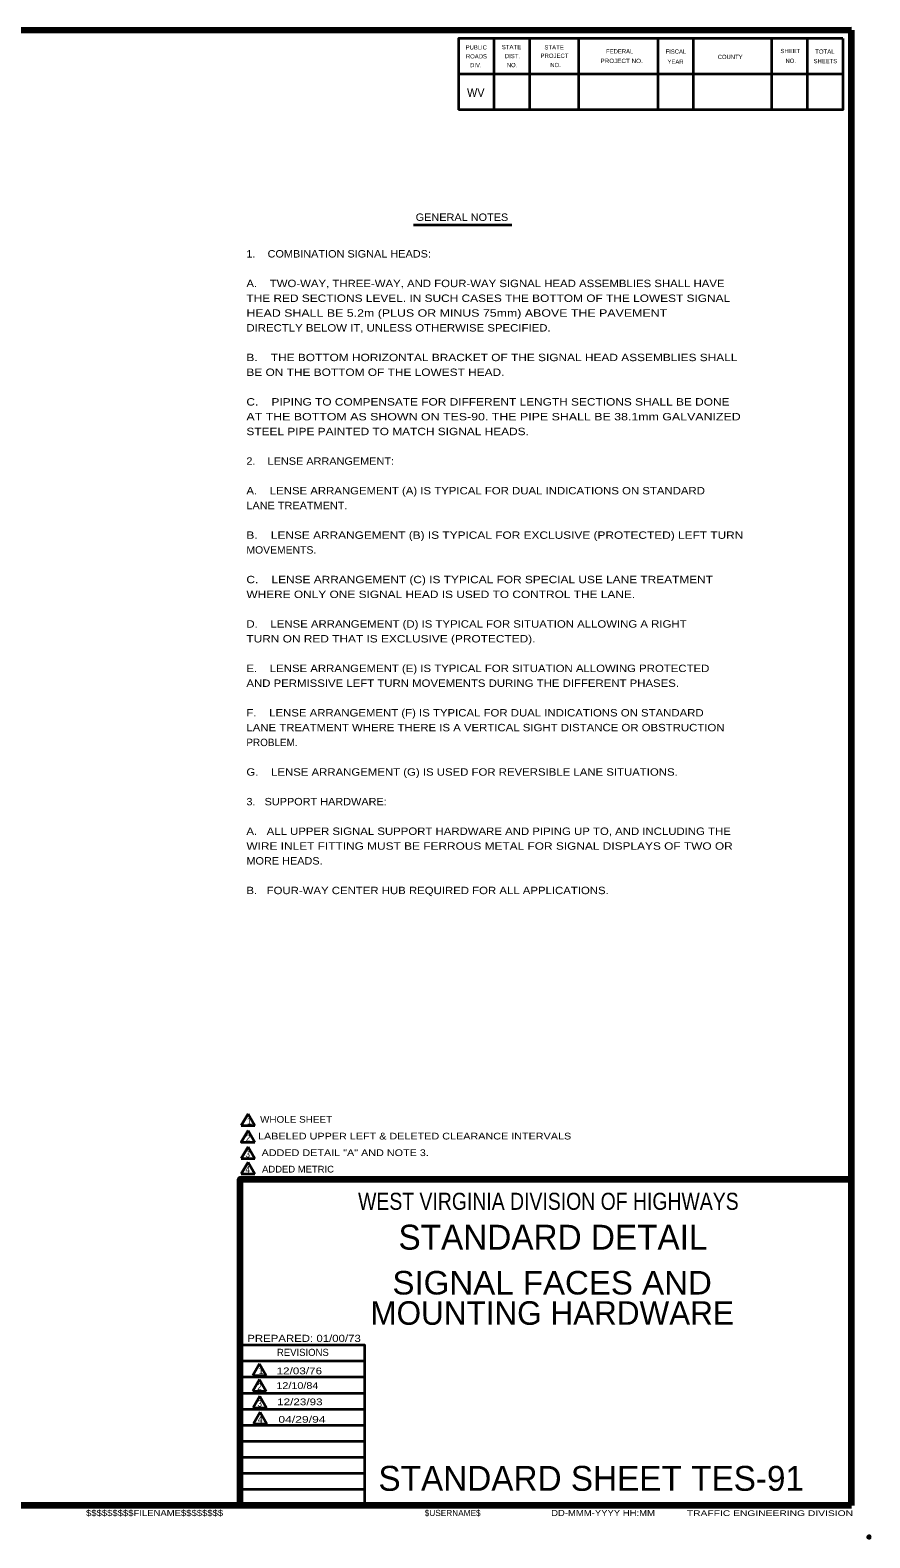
# Model space of a CAD drawing. Extents: x -382 to 473, y -132 to 412.
# Drawn here: x 174 to 473, y -132 to 406 of the extents above; entities that cross this region are included whole.
import ezdxf
from ezdxf.enums import TextEntityAlignment as Align

# ---------------------------------------------------------------- set-up
doc = ezdxf.new("R2010")
doc.units = 0
doc.header["$LTSCALE"] = 1.1
doc.header["$PDMODE"] = 32
doc.header["$PDSIZE"] = 0.55
doc.layers.add('1', color=7, linetype='Continuous', lineweight=53)
doc.layers.add('61', color=7, linetype='Continuous', lineweight=35)

msp = doc.modelspace()

# ---------------------------------------------------------------- linework, layer by layer
at = {"layer": '1', "lineweight": 158}
for q in [(466.693, 405.773), (466.693, -4.027), (-324.907, -120.327)]:
    msp.add_line((466.693, -120.327), q, dxfattribs=at)
at = {"layer": '1', "lineweight": 13}
msp.add_line((466.693, -120.327), (466.693, 405.773), dxfattribs=at)
at = {"layer": '1', "lineweight": 35}
for p, q in [((310.49, 336.296), (345.56, 336.296)), ((251.466, 19.314), (249.066, 15.157)), ((251.466, 19.314), (253.866, 15.157)), ((249.066, 15.157), (253.866, 15.157)), ((251.466, 13.329), (253.866, 9.172)), ((251.466, 7.523), (249.066, 3.367)), ((251.466, 7.523), (253.866, 3.367)), ((249.066, 3.367), (253.866, 3.367)), ((251.466, 2.033), (249.066, -2.123)), ((251.466, 2.033), (253.866, -2.123)), ((249.066, -2.123), (253.866, -2.123)), ((293.193, -68.927), (248.693, -68.927)), ((255.587, -69.839), (253.187, -73.996)), ((255.587, -69.839), (257.987, -73.996)), ((293.193, -74.627), (248.693, -74.627)), ((253.187, -73.996), (257.987, -73.996)), ((293.193, -80.427), (248.693, -80.427)), ((255.585, -75.449), (253.185, -79.606)), ((253.185, -79.606), (257.985, -79.606)), ((255.585, -75.449), (257.985, -79.606)), ((255.659, -81.36), (253.259, -85.517)), ((253.259, -85.517), (258.059, -85.517)), ((255.659, -81.36), (258.059, -85.517)), ((293.193, -86.127), (248.693, -86.127)), ((255.824, -87.07), (253.424, -91.227)), ((253.424, -91.227), (258.224, -91.227)), ((255.824, -87.07), (258.224, -91.227)), ((293.193, -91.827), (248.693, -91.827)), ((293.193, -97.527), (248.693, -97.527)), ((293.193, -103.227), (248.693, -103.227)), ((293.193, -108.927), (248.693, -108.927)), ((293.193, -114.627), (248.693, -114.627))]:
    msp.add_line(p, q, dxfattribs=at)
at = {"layer": '1', "lineweight": 158}
for points in [[(466.693, 405.773), (-325.007, 405.673), (-324.907, -120.327)], [(248.693, -120.327), (248.693, -4.027), (466.693, -4.027)]]:
    msp.add_lwpolyline(points, dxfattribs=at)
at = {"layer": '1', "lineweight": 35}
for points in [[(251.466, 13.329), (249.066, 9.172), (253.866, 9.172)], [(293.193, -120.327), (293.193, -63.227), (248.693, -63.227)]]:
    msp.add_lwpolyline(points, dxfattribs=at)
at = {"layer": '1'}
msp.add_point((472.993, -131.627), dxfattribs=at)
at = {"layer": '61'}
for p, q in [((339.193, 402.773), (339.193, 377.373)), ((351.893, 402.773), (351.893, 377.373)), ((369.293, 402.773), (369.293, 377.373)), ((397.593, 402.773), (397.593, 377.373)), ((410.293, 402.773), (410.293, 377.373)), ((438.193, 402.773), (438.193, 377.373)), ((450.893, 402.773), (450.893, 377.373)), ((463.593, 390.073), (326.493, 390.073))]:
    msp.add_line(p, q, dxfattribs=at)
at = {"layer": '61', "lineweight": 53}
for q in [(313.993, -120.327), (313.993, -120.327), (313.993, -120.327), (314.293, -120.327), (314.293, -120.327)]:
    msp.add_line((466.693, -120.327), q, dxfattribs=at)
at = {"layer": '61'}
for points in [[(463.593, 402.773), (326.493, 402.773), (326.493, 377.373)], [(463.593, 402.773), (463.593, 377.373), (326.493, 377.373)]]:
    msp.add_lwpolyline(points, dxfattribs=at)

# ---------------------------------------------------------------- texts
at = {"layer": '1'}
for s, height, width, p in [('WV', 3.048, 0.95, (329.593, 381.973)), ('1.    COMBINATION SIGNAL HEADS:', 2.64, 1.1, (250.896, 324.693)), ('A.    TWO-WAY, THREE-WAY, AND FOUR-WAY SIGNAL HEAD ASSEMBLIES SHALL HAVE', 2.64, 1.15, (250.896, 314.133)), ('THE RED SECTIONS LEVEL. IN SUCH CASES THE BOTTOM OF THE LOWEST SIGNAL', 2.64, 1.2, (250.896, 308.853)), ('HEAD SHALL BE 5.2m (PLUS OR MINUS 75mm) ABOVE THE PAVEMENT', 2.64, 1.25, (250.896, 303.573)), ('DIRECTLY BELOW IT, UNLESS OTHERWISE SPECIFIED.', 2.64, 1.15, (250.896, 298.293)), ('B.    THE BOTTOM HORIZONTAL BRACKET OF THE SIGNAL HEAD ASSEMBLIES SHALL', 2.64, 1.2, (250.896, 287.733)), ('BE ON THE BOTTOM OF THE LOWEST HEAD.', 2.64, 1.2, (250.896, 282.453)), ('C.    PIPING TO COMPENSATE FOR DIFFERENT LENGTH SECTIONS SHALL BE DONE', 2.64, 1.2, (250.896, 271.893)), ('AT THE BOTTOM AS SHOWN ON TES-90. THE PIPE SHALL BE 38.1mm GALVANIZED', 2.64, 1.25, (250.896, 266.613)), ('STEEL PIPE PAINTED TO MATCH SIGNAL HEADS.', 2.64, 1.2, (250.896, 261.333)), ('2.    LENSE ARRANGEMENT:', 2.64, 1.1, (250.896, 250.773)), ('A.    LENSE ARRANGEMENT (A) IS TYPICAL FOR DUAL INDICATIONS ON STANDARD', 2.64, 1.15, (250.896, 240.213)), ('LANE TREATMENT.', 2.64, 1.1, (250.896, 234.933)), ('B.    LENSE ARRANGEMENT (B) IS TYPICAL FOR EXCLUSIVE (PROTECTED) LEFT TURN', 2.64, 1.2, (250.896, 224.373)), ('MOVEMENTS.', 2.64, 1.05, (250.896, 219.093)), ('C.    LENSE ARRANGEMENT (C) IS TYPICAL FOR SPECIAL USE LANE TREATMENT', 2.64, 1.2, (250.896, 208.533)), ('WHERE ONLY ONE SIGNAL HEAD IS USED TO CONTROL THE LANE.', 2.64, 1.2, (250.896, 203.253)), ('D.    LENSE ARRANGEMENT (D) IS TYPICAL FOR SITUATION ALLOWING A RIGHT', 2.64, 1.15, (250.896, 192.693)), ('TURN ON RED THAT IS EXCLUSIVE (PROTECTED).', 2.64, 1.2, (250.896, 187.413)), ('E.    LENSE ARRANGEMENT (E) IS TYPICAL FOR SITUATION ALLOWING PROTECTED', 2.64, 1.15, (250.896, 176.853)), ('AND PERMISSIVE LEFT TURN MOVEMENTS DURING THE DIFFERENT PHASES.', 2.64, 1.15, (250.896, 171.573)), ('F.    LENSE ARRANGEMENT (F) IS TYPICAL FOR DUAL INDICATIONS ON STANDARD', 2.64, 1.15, (250.896, 161.013)), ('LANE TREATMENT WHERE THERE IS A VERTICAL SIGHT DISTANCE OR OBSTRUCTION', 2.64, 1.15, (250.896, 155.733)), ('G.    LENSE ARRANGEMENT (G) IS USED FOR REVERSIBLE LANE SITUATIONS.', 2.64, 1.15, (250.896, 139.893)), ('3.   SUPPORT HARDWARE:', 2.64, 1.1, (250.896, 129.333)), ('A.   ALL UPPER SIGNAL SUPPORT HARDWARE AND PIPING UP TO, AND INCLUDING THE', 2.64, 1.15, (250.896, 118.773)), ('WIRE INLET FITTING MUST BE FERROUS METAL FOR SIGNAL DISPLAYS OF TWO OR', 2.64, 1.2, (250.896, 113.493)), ('MORE HEADS.', 2.64, 1.1, (250.896, 108.213)), ('B.   FOUR-WAY CENTER HUB REQUIRED FOR ALL APPLICATIONS.', 2.64, 1.15, (250.896, 97.653)), ('PREPARED: 01/00/73', 2.537, 1.2, (251.193, -62.027)), ('12/03/76', 2.397, 1.3, (261.661, -73.553)), ('12/10/84', 2.397, 1.2, (261.585, -78.788)), ('12/23/93', 2.397, 1.3, (261.848, -84.605)), ('04/29/94', 2.397, 1.35, (262.288, -90.864)), ('$$$$$$$$$FILENAME$$$$$$$$', 2.2, 1.15, (193.693, -124.127)), ('DD-MMM-YYYY HH:MM', 2.2, 1.15, (359.593, -124.127)), ('TRAFFIC ENGINEERING DIVISION', 2.031, 1.35, (407.993, -124.127))]:
    msp.add_text(s, height=height, dxfattribs=dict(at, width=width)).set_placement(p)
for s, height, width, p in [('GENERAL NOTES', 2.64, 1.1, (327.777, 337.749)), ('WHOLE SHEET', 2.4, 1.1, (268.621, 16.138)), ('2', 2.4, 0.9, (251.49, 9.507)), ('LABELED UPPER LEFT & DELETED CLEARANCE INTERVALS', 2.4, 1.2, (310.89, 10.163)), ('3', 2.4, 0.9, (251.359, 3.757)), ('ADDED DETAIL "A" AND NOTE 3.', 2.4, 1.2, (286.139, 4.239)), ('4', 2.4, 0.95, (251.368, -1.734)), ('ADDED METRIC', 2.4, 1.05, (269.307, -1.617)), ('WEST VIRGINIA DIVISION OF HIGHWAYS', 6.089, 0.85, (358.593, -14.927)), ('SIGNAL FACES AND', 8.391, 1.05, (359.947, -45.123)), ('2', 2.4, 0.9, (255.572, -79.227)), ('3', 2.4, 0.9, (255.645, -85.138)), ('4', 2.4, 0.95, (255.82, -90.849))]:
    msp.add_text(s, height=height, dxfattribs=dict(at, width=width)).set_placement(p, align=Align.CENTER)
for s, height, p in [('PROBLEM.', 2.64, (250.896, 150.453)), ('REVISIONS', 2.537, (261.793, -67.027)), ('STANDARD SHEET TES-91', 8.881, (297.993, -115.127)), ('$USERNAME$', 2.2, (314.493, -124.127))]:
    msp.add_text(s, height=height, dxfattribs=at).set_placement(p)
for s, height, p in [('1', 2.4, (251.976, 15.547)), ('STANDARD DETAIL', 8.881, (360.243, -29.127)), ('MOUNTING HARDWARE', 8.391, (359.947, -55.915)), ('1', 2.4, (256.115, -73.468))]:
    msp.add_text(s, height=height, dxfattribs=at).set_placement(p, align=Align.CENTER)
at = {"layer": '61'}
for s, height, rotation, p in [('PUBLIC', 1.525, 0.033, (329.093, 398.873)), ('FEDERAL', 1.523, 0.007, (379.193, 397.473)), ('FISCAL', 1.525, 359.942, (400.393, 397.373)), ('SHEET', 1.525, 0.059, (441.393, 397.573)), ('ROADS', 1.525, 0.124, (329.193, 395.673)), ('DIV.', 1.525, 359.932, (330.693, 392.573)), ('DIST.', 1.525, 0.056, (343.093, 395.773)), ('YEAR', 1.523, 0.105, (401.093, 393.773)), ('COUNTY', 1.523, 0.069, (418.993, 395.473)), ('SHEETS', 1.523, 359.959, (453.193, 393.973))]:
    msp.add_text(s, height=height, rotation=rotation, dxfattribs=at).set_placement(p)
for s, rotation, width, p in [('STATE', 0.059, 1.05, (341.993, 398.973)), ('STATE', 0.059, 1.05, (357.193, 398.873)), ('TOTAL', 359.926, 1.05, (453.793, 397.373)), ('NO.', 359.852, 0.9, (343.793, 392.573)), ('PROJECT', 359.908, 1.05, (355.793, 395.873)), ('NO.', 0.225, 0.9, (359.293, 392.573)), ('PROJECT NO.', 359.922, 1.1, (377.193, 394.073)), ('NO.', 359.852, 0.9, (443.193, 394.073))]:
    msp.add_text(s, height=1.525, rotation=rotation, dxfattribs=dict(at, width=width)).set_placement(p)

doc.saveas('drawing.dxf')
